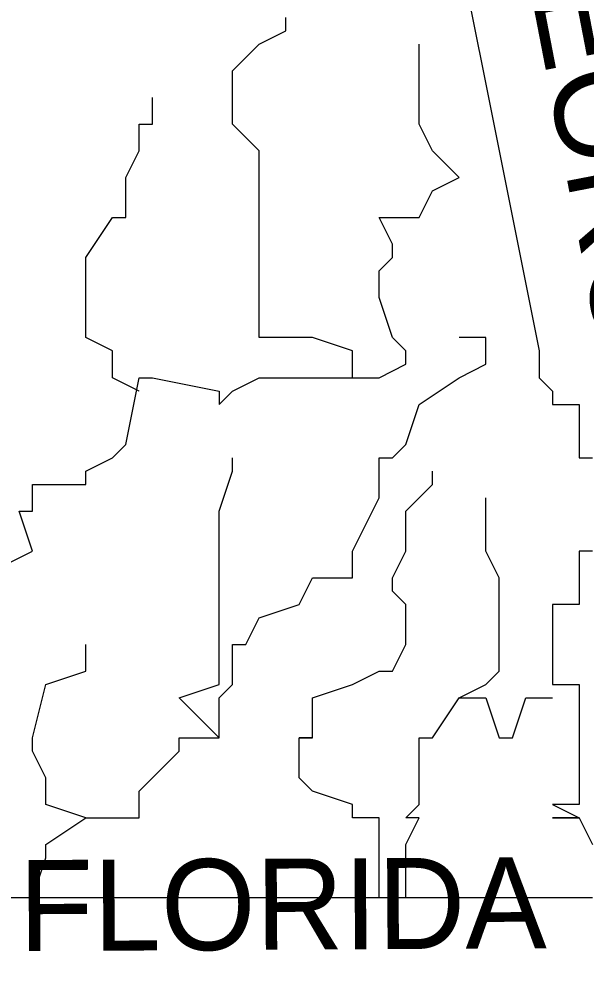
# Model space of a CAD drawing. Extents: x 1797478 to 1805176, y 246529 to 250952.
# Drawn here: x 1802981.062 to 1802983.296, y 250072.194 to 250075.933 of the extents above; entities that cross this region are included whole.
import ezdxf

# ---------------------------------------------------------------- set-up
doc = ezdxf.new("R2010")
doc.units = 0
doc.layers.add('great seal', color=7, linetype='Continuous')

msp = doc.modelspace()

# ---------------------------------------------------------------- linework, layer by layer
at = {"layer": 'great seal'}
msp.add_line((1802981.5349, 250074.4676), (1802981.5349, 250074.4676), dxfattribs=at)
msp.add_line((1802981.5349, 250074.4676), (1802981.5349, 250074.4676), dxfattribs=at)
msp.add_line((1802981.5349, 250074.4676), (1802981.5349, 250074.4676), dxfattribs=at)
msp.add_line((1802981.5349, 250074.4676), (1802981.5349, 250074.4676), dxfattribs=at)
msp.add_line((1802981.5349, 250074.4676), (1802981.5349, 250074.4676), dxfattribs=at)
msp.add_line((1802981.5349, 250074.4676), (1802981.5349, 250074.4676), dxfattribs=at)
for points in [[(1802979.7481, 250071.7875), (1802979.7481, 250073.6268), (1802980.2211, 250076.8851), (1802980.2211, 250076.9902), (1802980.2211, 250076.9902), (1802980.2211, 250076.9902), (1802980.0634, 250076.9902), (1802980.0634, 250077.0427), (1802980.2211, 250077.0427), (1802982.6385, 250076.9902), (1802983.1115, 250074.6253), (1802983.1115, 250074.5202), (1802983.164, 250074.4676), (1802983.164, 250074.4151), (1802983.164, 250074.4151), (1802983.2691, 250074.4151), (1802983.2691, 250074.2574), (1802983.2691, 250074.2049), (1802983.3217, 250074.2049)], [(1802979.7481, 250071.7875), (1802979.7481, 250073.6268), (1802980.2211, 250076.8851), (1802980.2211, 250076.9902), (1802980.2211, 250076.9902), (1802980.2211, 250076.9902), (1802980.0634, 250076.9902), (1802980.0634, 250077.0427), (1802980.2211, 250077.0427), (1802982.6385, 250076.9902), (1802983.1115, 250074.6253), (1802983.1115, 250074.5202), (1802983.164, 250074.4676), (1802983.164, 250074.4151), (1802983.164, 250074.4151), (1802983.2691, 250074.4151), (1802983.2691, 250074.2574), (1802983.2691, 250074.2049), (1802983.3217, 250074.2049)], [(1802979.7481, 250071.7875), (1802979.7481, 250073.6268), (1802980.2211, 250076.8851), (1802980.2211, 250076.9902), (1802980.2211, 250076.9902), (1802980.2211, 250076.9902), (1802980.0634, 250076.9902), (1802980.0634, 250077.0427), (1802980.2211, 250077.0427), (1802982.6385, 250076.9902), (1802983.1115, 250074.6253), (1802983.1115, 250074.5202), (1802983.164, 250074.4676), (1802983.164, 250074.4151), (1802983.164, 250074.4151), (1802983.2691, 250074.4151), (1802983.2691, 250074.2574), (1802983.2691, 250074.2049), (1802983.3217, 250074.2049)], [(1802982.3757, 250074.5202), (1802982.3757, 250074.6253), (1802982.2181, 250074.6779), (1802982.1655, 250074.6779), (1802982.0079, 250074.6779), (1802982.0079, 250074.9406), (1802982.0079, 250074.9406), (1802982.0079, 250074.9932), (1802982.0079, 250075.1508), (1802982.0079, 250075.2559), (1802982.0079, 250075.4136), (1802981.9028, 250075.5187), (1802981.9028, 250075.7289), (1802982.0079, 250075.834), (1802982.113, 250075.8866), (1802982.113, 250075.9391)], [(1802982.3757, 250074.5202), (1802982.3757, 250074.6253), (1802982.2181, 250074.6779), (1802982.1655, 250074.6779), (1802982.0079, 250074.6779), (1802982.0079, 250074.9406), (1802982.0079, 250074.9406), (1802982.0079, 250074.9932), (1802982.0079, 250075.1508), (1802982.0079, 250075.2559), (1802982.0079, 250075.4136), (1802981.9028, 250075.5187), (1802981.9028, 250075.7289), (1802982.0079, 250075.834), (1802982.113, 250075.8866), (1802982.113, 250075.9391)], [(1802982.3757, 250074.5202), (1802982.3757, 250074.6253), (1802982.2181, 250074.6779), (1802982.1655, 250074.6779), (1802982.0079, 250074.6779), (1802982.0079, 250074.9406), (1802982.0079, 250074.9406), (1802982.0079, 250074.9932), (1802982.0079, 250075.1508), (1802982.0079, 250075.2559), (1802982.0079, 250075.4136), (1802981.9028, 250075.5187), (1802981.9028, 250075.7289), (1802982.0079, 250075.834), (1802982.113, 250075.8866), (1802982.113, 250075.9391)], [(1802981.0094, 250073.7845), (1802981.1145, 250073.837), (1802981.0619, 250073.9947), (1802981.1145, 250073.9947), (1802981.1145, 250074.0998), (1802981.3247, 250074.0998), (1802981.3247, 250074.1523), (1802981.3247, 250074.1523), (1802981.4298, 250074.2049), (1802981.4823, 250074.2574), (1802981.5349, 250074.5202), (1802981.5874, 250074.5202), (1802981.8502, 250074.4676), (1802981.8502, 250074.4151), (1802981.9028, 250074.4676), (1802982.0079, 250074.5202), (1802982.1655, 250074.5202), (1802982.3757, 250074.5202), (1802982.4808, 250074.5202), (1802982.5859, 250074.5728), (1802982.5859, 250074.6253), (1802982.5334, 250074.6779), (1802982.5334, 250074.6779), (1802982.4808, 250074.8355), (1802982.4808, 250074.9406), (1802982.5334, 250074.9932), (1802982.5334, 250075.0457), (1802982.4808, 250075.1508), (1802982.6385, 250075.1508), (1802982.691, 250075.2559), (1802982.7962, 250075.3085), (1802982.691, 250075.4136), (1802982.691, 250075.4136), (1802982.6385, 250075.5187), (1802982.6385, 250075.6238), (1802982.6385, 250075.834)], [(1802981.0094, 250073.7845), (1802981.1145, 250073.837), (1802981.0619, 250073.9947), (1802981.1145, 250073.9947), (1802981.1145, 250074.0998), (1802981.3247, 250074.0998), (1802981.3247, 250074.1523), (1802981.3247, 250074.1523), (1802981.4298, 250074.2049), (1802981.4823, 250074.2574), (1802981.5349, 250074.5202), (1802981.5874, 250074.5202), (1802981.8502, 250074.4676), (1802981.8502, 250074.4151), (1802981.9028, 250074.4676), (1802982.0079, 250074.5202), (1802982.1655, 250074.5202), (1802982.3757, 250074.5202), (1802982.4808, 250074.5202), (1802982.5859, 250074.5728), (1802982.5859, 250074.6253), (1802982.5334, 250074.6779), (1802982.5334, 250074.6779), (1802982.4808, 250074.8355), (1802982.4808, 250074.9406), (1802982.5334, 250074.9932), (1802982.5334, 250075.0457), (1802982.4808, 250075.1508), (1802982.6385, 250075.1508), (1802982.691, 250075.2559), (1802982.7962, 250075.3085), (1802982.691, 250075.4136), (1802982.691, 250075.4136), (1802982.6385, 250075.5187), (1802982.6385, 250075.6238), (1802982.6385, 250075.834)], [(1802981.0094, 250073.7845), (1802981.1145, 250073.837), (1802981.0619, 250073.9947), (1802981.1145, 250073.9947), (1802981.1145, 250074.0998), (1802981.3247, 250074.0998), (1802981.3247, 250074.1523), (1802981.3247, 250074.1523), (1802981.4298, 250074.2049), (1802981.4823, 250074.2574), (1802981.5349, 250074.5202), (1802981.5874, 250074.5202), (1802981.8502, 250074.4676), (1802981.8502, 250074.4151), (1802981.9028, 250074.4676), (1802982.0079, 250074.5202), (1802982.1655, 250074.5202), (1802982.3757, 250074.5202), (1802982.4808, 250074.5202), (1802982.5859, 250074.5728), (1802982.5859, 250074.6253), (1802982.5334, 250074.6779), (1802982.5334, 250074.6779), (1802982.4808, 250074.8355), (1802982.4808, 250074.9406), (1802982.5334, 250074.9932), (1802982.5334, 250075.0457), (1802982.4808, 250075.1508), (1802982.6385, 250075.1508), (1802982.691, 250075.2559), (1802982.7962, 250075.3085), (1802982.691, 250075.4136), (1802982.691, 250075.4136), (1802982.6385, 250075.5187), (1802982.6385, 250075.6238), (1802982.6385, 250075.834)], [(1802981.5349, 250074.4676), (1802981.4298, 250074.5202), (1802981.4298, 250074.5728), (1802981.4298, 250074.6253), (1802981.3247, 250074.6779), (1802981.3247, 250074.8355), (1802981.3247, 250074.9406), (1802981.3247, 250074.9932), (1802981.3247, 250074.9932), (1802981.4298, 250075.1508), (1802981.4823, 250075.1508), (1802981.4823, 250075.3085), (1802981.5349, 250075.4136), (1802981.5349, 250075.4136), (1802981.5349, 250075.5187), (1802981.5874, 250075.5187), (1802981.5874, 250075.6238)], [(1802981.5349, 250074.4676), (1802981.4298, 250074.5202), (1802981.4298, 250074.5728), (1802981.4298, 250074.6253), (1802981.3247, 250074.6779), (1802981.3247, 250074.8355), (1802981.3247, 250074.9406), (1802981.3247, 250074.9932), (1802981.3247, 250074.9932), (1802981.4298, 250075.1508), (1802981.4823, 250075.1508), (1802981.4823, 250075.3085), (1802981.5349, 250075.4136), (1802981.5349, 250075.4136), (1802981.5349, 250075.5187), (1802981.5874, 250075.5187), (1802981.5874, 250075.6238)], [(1802981.5349, 250074.4676), (1802981.4298, 250074.5202), (1802981.4298, 250074.5728), (1802981.4298, 250074.6253), (1802981.3247, 250074.6779), (1802981.3247, 250074.8355), (1802981.3247, 250074.9406), (1802981.3247, 250074.9932), (1802981.3247, 250074.9932), (1802981.4298, 250075.1508), (1802981.4823, 250075.1508), (1802981.4823, 250075.3085), (1802981.5349, 250075.4136), (1802981.5349, 250075.4136), (1802981.5349, 250075.5187), (1802981.5874, 250075.5187), (1802981.5874, 250075.6238)], [(1802981.8502, 250073.1013), (1802981.8502, 250073.1013), (1802981.8502, 250073.2589), (1802981.9028, 250073.3115), (1802981.9028, 250073.364), (1802981.9028, 250073.4691), (1802981.9553, 250073.4691), (1802982.0079, 250073.5743), (1802982.1655, 250073.6268), (1802982.2181, 250073.7319), (1802982.3757, 250073.7319), (1802982.3757, 250073.837), (1802982.4808, 250074.0472), (1802982.4808, 250074.1523), (1802982.4808, 250074.1523), (1802982.4808, 250074.2049), (1802982.5334, 250074.2049), (1802982.5859, 250074.2574), (1802982.6385, 250074.4151), (1802982.7962, 250074.5202), (1802982.9013, 250074.5728), (1802982.9013, 250074.6253), (1802982.9013, 250074.6779), (1802982.7962, 250074.6779)], [(1802981.8502, 250073.1013), (1802981.8502, 250073.1013), (1802981.8502, 250073.2589), (1802981.9028, 250073.3115), (1802981.9028, 250073.364), (1802981.9028, 250073.4691), (1802981.9553, 250073.4691), (1802982.0079, 250073.5743), (1802982.1655, 250073.6268), (1802982.2181, 250073.7319), (1802982.3757, 250073.7319), (1802982.3757, 250073.837), (1802982.4808, 250074.0472), (1802982.4808, 250074.1523), (1802982.4808, 250074.1523), (1802982.4808, 250074.2049), (1802982.5334, 250074.2049), (1802982.5859, 250074.2574), (1802982.6385, 250074.4151), (1802982.7962, 250074.5202), (1802982.9013, 250074.5728), (1802982.9013, 250074.6253), (1802982.9013, 250074.6779), (1802982.7962, 250074.6779)], [(1802981.8502, 250073.1013), (1802981.8502, 250073.1013), (1802981.8502, 250073.2589), (1802981.9028, 250073.3115), (1802981.9028, 250073.364), (1802981.9028, 250073.4691), (1802981.9553, 250073.4691), (1802982.0079, 250073.5743), (1802982.1655, 250073.6268), (1802982.2181, 250073.7319), (1802982.3757, 250073.7319), (1802982.3757, 250073.837), (1802982.4808, 250074.0472), (1802982.4808, 250074.1523), (1802982.4808, 250074.1523), (1802982.4808, 250074.2049), (1802982.5334, 250074.2049), (1802982.5859, 250074.2574), (1802982.6385, 250074.4151), (1802982.7962, 250074.5202), (1802982.9013, 250074.5728), (1802982.9013, 250074.6253), (1802982.9013, 250074.6779), (1802982.7962, 250074.6779)], [(1802981.3247, 250072.786), (1802981.3247, 250072.786), (1802981.4298, 250072.786), (1802981.4823, 250072.786), (1802981.5349, 250072.786), (1802981.5349, 250072.8385), (1802981.5349, 250072.8911), (1802981.5874, 250072.9436), (1802981.6925, 250073.0487), (1802981.6925, 250073.1013), (1802981.8502, 250073.1013), (1802981.8502, 250073.1013), (1802981.6925, 250073.2589), (1802981.8502, 250073.3115), (1802981.8502, 250073.364), (1802981.8502, 250073.4691), (1802981.8502, 250073.5743), (1802981.8502, 250073.6268), (1802981.8502, 250073.7319), (1802981.8502, 250073.7319), (1802981.8502, 250073.837), (1802981.8502, 250073.9947), (1802981.9028, 250074.1523), (1802981.9028, 250074.1523), (1802981.9028, 250074.2049)], [(1802981.3247, 250072.786), (1802981.3247, 250072.786), (1802981.4298, 250072.786), (1802981.4823, 250072.786), (1802981.5349, 250072.786), (1802981.5349, 250072.8385), (1802981.5349, 250072.8911), (1802981.5874, 250072.9436), (1802981.6925, 250073.0487), (1802981.6925, 250073.1013), (1802981.8502, 250073.1013), (1802981.8502, 250073.1013), (1802981.6925, 250073.2589), (1802981.8502, 250073.3115), (1802981.8502, 250073.364), (1802981.8502, 250073.4691), (1802981.8502, 250073.5743), (1802981.8502, 250073.6268), (1802981.8502, 250073.7319), (1802981.8502, 250073.7319), (1802981.8502, 250073.837), (1802981.8502, 250073.9947), (1802981.9028, 250074.1523), (1802981.9028, 250074.1523), (1802981.9028, 250074.2049)], [(1802981.3247, 250072.786), (1802981.3247, 250072.786), (1802981.4298, 250072.786), (1802981.4823, 250072.786), (1802981.5349, 250072.786), (1802981.5349, 250072.8385), (1802981.5349, 250072.8911), (1802981.5874, 250072.9436), (1802981.6925, 250073.0487), (1802981.6925, 250073.1013), (1802981.8502, 250073.1013), (1802981.8502, 250073.1013), (1802981.6925, 250073.2589), (1802981.8502, 250073.3115), (1802981.8502, 250073.364), (1802981.8502, 250073.4691), (1802981.8502, 250073.5743), (1802981.8502, 250073.6268), (1802981.8502, 250073.7319), (1802981.8502, 250073.7319), (1802981.8502, 250073.837), (1802981.8502, 250073.9947), (1802981.9028, 250074.1523), (1802981.9028, 250074.1523), (1802981.9028, 250074.2049)], [(1802982.4808, 250072.4706), (1802982.4808, 250072.6283), (1802982.4808, 250072.6809), (1802982.4808, 250072.786), (1802982.4808, 250072.786), (1802982.3757, 250072.786), (1802982.3757, 250072.8385), (1802982.2181, 250072.8911), (1802982.1655, 250072.9436), (1802982.1655, 250073.0487), (1802982.1655, 250073.1013), (1802982.2181, 250073.1013), (1802982.1655, 250073.1013), (1802982.2181, 250073.1013), (1802982.2181, 250073.2589), (1802982.3757, 250073.3115), (1802982.4808, 250073.364), (1802982.4808, 250073.364), (1802982.5334, 250073.364), (1802982.5859, 250073.4691), (1802982.5859, 250073.4691), (1802982.5859, 250073.5743), (1802982.5859, 250073.6268), (1802982.5859, 250073.6268), (1802982.5334, 250073.6794), (1802982.5334, 250073.7319), (1802982.5859, 250073.837), (1802982.5859, 250073.9947), (1802982.6385, 250074.0472), (1802982.691, 250074.0998), (1802982.691, 250074.1523)], [(1802982.4808, 250072.4706), (1802982.4808, 250072.6283), (1802982.4808, 250072.6809), (1802982.4808, 250072.786), (1802982.4808, 250072.786), (1802982.3757, 250072.786), (1802982.3757, 250072.8385), (1802982.2181, 250072.8911), (1802982.1655, 250072.9436), (1802982.1655, 250073.0487), (1802982.1655, 250073.1013), (1802982.2181, 250073.1013), (1802982.1655, 250073.1013), (1802982.2181, 250073.1013), (1802982.2181, 250073.2589), (1802982.3757, 250073.3115), (1802982.4808, 250073.364), (1802982.4808, 250073.364), (1802982.5334, 250073.364), (1802982.5859, 250073.4691), (1802982.5859, 250073.4691), (1802982.5859, 250073.5743), (1802982.5859, 250073.6268), (1802982.5859, 250073.6268), (1802982.5334, 250073.6794), (1802982.5334, 250073.7319), (1802982.5859, 250073.837), (1802982.5859, 250073.9947), (1802982.6385, 250074.0472), (1802982.691, 250074.0998), (1802982.691, 250074.1523)], [(1802982.4808, 250072.4706), (1802982.4808, 250072.6283), (1802982.4808, 250072.6809), (1802982.4808, 250072.786), (1802982.4808, 250072.786), (1802982.3757, 250072.786), (1802982.3757, 250072.8385), (1802982.2181, 250072.8911), (1802982.1655, 250072.9436), (1802982.1655, 250073.0487), (1802982.1655, 250073.1013), (1802982.2181, 250073.1013), (1802982.1655, 250073.1013), (1802982.2181, 250073.1013), (1802982.2181, 250073.2589), (1802982.3757, 250073.3115), (1802982.4808, 250073.364), (1802982.4808, 250073.364), (1802982.5334, 250073.364), (1802982.5859, 250073.4691), (1802982.5859, 250073.4691), (1802982.5859, 250073.5743), (1802982.5859, 250073.6268), (1802982.5859, 250073.6268), (1802982.5334, 250073.6794), (1802982.5334, 250073.7319), (1802982.5859, 250073.837), (1802982.5859, 250073.9947), (1802982.6385, 250074.0472), (1802982.691, 250074.0998), (1802982.691, 250074.1523)], [(1802982.7962, 250073.2589), (1802982.7962, 250073.2589), (1802982.9013, 250073.3115), (1802982.9538, 250073.364), (1802982.9538, 250073.364), (1802982.9538, 250073.4691), (1802982.9538, 250073.5743), (1802982.9538, 250073.6268), (1802982.9538, 250073.6794), (1802982.9538, 250073.7319), (1802982.9013, 250073.837), (1802982.9013, 250073.837), (1802982.9013, 250074.0472)], [(1802982.7962, 250073.2589), (1802982.7962, 250073.2589), (1802982.9013, 250073.3115), (1802982.9538, 250073.364), (1802982.9538, 250073.364), (1802982.9538, 250073.4691), (1802982.9538, 250073.5743), (1802982.9538, 250073.6268), (1802982.9538, 250073.6794), (1802982.9538, 250073.7319), (1802982.9013, 250073.837), (1802982.9013, 250073.837), (1802982.9013, 250074.0472)], [(1802982.7962, 250073.2589), (1802982.7962, 250073.2589), (1802982.9013, 250073.3115), (1802982.9538, 250073.364), (1802982.9538, 250073.364), (1802982.9538, 250073.4691), (1802982.9538, 250073.5743), (1802982.9538, 250073.6268), (1802982.9538, 250073.6794), (1802982.9538, 250073.7319), (1802982.9013, 250073.837), (1802982.9013, 250073.837), (1802982.9013, 250074.0472)], [(1802983.3217, 250073.837), (1802983.2691, 250073.837), (1802983.2691, 250073.837), (1802983.2691, 250073.837), (1802983.2691, 250073.7845), (1802983.2691, 250073.7319), (1802983.2691, 250073.7319), (1802983.2691, 250073.7319), (1802983.2691, 250073.7319), (1802983.2691, 250073.7319), (1802983.2691, 250073.6794), (1802983.2691, 250073.6794), (1802983.2691, 250073.6794), (1802983.2691, 250073.6268), (1802983.2691, 250073.6268), (1802983.164, 250073.6268), (1802983.164, 250073.6268), (1802983.164, 250073.6268), (1802983.164, 250073.5743), (1802983.164, 250073.5743), (1802983.164, 250073.4691), (1802983.164, 250073.4691), (1802983.164, 250073.4691), (1802983.164, 250073.4691), (1802983.164, 250073.4691), (1802983.164, 250073.4691), (1802983.164, 250073.4691), (1802983.164, 250073.364), (1802983.164, 250073.364), (1802983.164, 250073.364), (1802983.164, 250073.364), (1802983.164, 250073.364), (1802983.164, 250073.364), (1802983.164, 250073.3115), (1802983.2691, 250073.3115), (1802983.2691, 250073.2589), (1802983.2691, 250073.2589), (1802983.2691, 250073.2589), (1802983.2691, 250073.1013), (1802983.2691, 250073.1013), (1802983.2691, 250073.1013), (1802983.2691, 250073.1013), (1802983.2691, 250073.1013), (1802983.2691, 250073.1013), (1802983.2691, 250073.0487), (1802983.2691, 250072.9436), (1802983.2691, 250072.9436), (1802983.2691, 250072.9436), (1802983.2691, 250072.8911), (1802983.2691, 250072.8911), (1802983.2691, 250072.8385), (1802983.2691, 250072.8385), (1802983.164, 250072.8385), (1802983.164, 250072.8385), (1802983.164, 250072.8385), (1802983.164, 250072.8385), (1802983.2691, 250072.786), (1802983.2691, 250072.786), (1802983.164, 250072.786), (1802983.2691, 250072.786), (1802983.2691, 250072.786), (1802983.2691, 250072.786), (1802983.3217, 250072.6809)], [(1802983.3217, 250073.837), (1802983.2691, 250073.837), (1802983.2691, 250073.837), (1802983.2691, 250073.837), (1802983.2691, 250073.7845), (1802983.2691, 250073.7319), (1802983.2691, 250073.7319), (1802983.2691, 250073.7319), (1802983.2691, 250073.7319), (1802983.2691, 250073.7319), (1802983.2691, 250073.6794), (1802983.2691, 250073.6794), (1802983.2691, 250073.6794), (1802983.2691, 250073.6268), (1802983.2691, 250073.6268), (1802983.164, 250073.6268), (1802983.164, 250073.6268), (1802983.164, 250073.6268), (1802983.164, 250073.5743), (1802983.164, 250073.5743), (1802983.164, 250073.4691), (1802983.164, 250073.4691), (1802983.164, 250073.4691), (1802983.164, 250073.4691), (1802983.164, 250073.4691), (1802983.164, 250073.4691), (1802983.164, 250073.4691), (1802983.164, 250073.364), (1802983.164, 250073.364), (1802983.164, 250073.364), (1802983.164, 250073.364), (1802983.164, 250073.364), (1802983.164, 250073.364), (1802983.164, 250073.3115), (1802983.2691, 250073.3115), (1802983.2691, 250073.2589), (1802983.2691, 250073.2589), (1802983.2691, 250073.2589), (1802983.2691, 250073.1013), (1802983.2691, 250073.1013), (1802983.2691, 250073.1013), (1802983.2691, 250073.1013), (1802983.2691, 250073.1013), (1802983.2691, 250073.1013), (1802983.2691, 250073.0487), (1802983.2691, 250072.9436), (1802983.2691, 250072.9436), (1802983.2691, 250072.9436), (1802983.2691, 250072.8911), (1802983.2691, 250072.8911), (1802983.2691, 250072.8385), (1802983.2691, 250072.8385), (1802983.164, 250072.8385), (1802983.164, 250072.8385), (1802983.164, 250072.8385), (1802983.164, 250072.8385), (1802983.2691, 250072.786), (1802983.2691, 250072.786), (1802983.164, 250072.786), (1802983.2691, 250072.786), (1802983.2691, 250072.786), (1802983.2691, 250072.786), (1802983.3217, 250072.6809)], [(1802983.3217, 250073.837), (1802983.2691, 250073.837), (1802983.2691, 250073.837), (1802983.2691, 250073.837), (1802983.2691, 250073.7845), (1802983.2691, 250073.7319), (1802983.2691, 250073.7319), (1802983.2691, 250073.7319), (1802983.2691, 250073.7319), (1802983.2691, 250073.7319), (1802983.2691, 250073.6794), (1802983.2691, 250073.6794), (1802983.2691, 250073.6794), (1802983.2691, 250073.6268), (1802983.2691, 250073.6268), (1802983.164, 250073.6268), (1802983.164, 250073.6268), (1802983.164, 250073.6268), (1802983.164, 250073.5743), (1802983.164, 250073.5743), (1802983.164, 250073.4691), (1802983.164, 250073.4691), (1802983.164, 250073.4691), (1802983.164, 250073.4691), (1802983.164, 250073.4691), (1802983.164, 250073.4691), (1802983.164, 250073.4691), (1802983.164, 250073.364), (1802983.164, 250073.364), (1802983.164, 250073.364), (1802983.164, 250073.364), (1802983.164, 250073.364), (1802983.164, 250073.364), (1802983.164, 250073.3115), (1802983.2691, 250073.3115), (1802983.2691, 250073.2589), (1802983.2691, 250073.2589), (1802983.2691, 250073.2589), (1802983.2691, 250073.1013), (1802983.2691, 250073.1013), (1802983.2691, 250073.1013), (1802983.2691, 250073.1013), (1802983.2691, 250073.1013), (1802983.2691, 250073.1013), (1802983.2691, 250073.0487), (1802983.2691, 250072.9436), (1802983.2691, 250072.9436), (1802983.2691, 250072.9436), (1802983.2691, 250072.8911), (1802983.2691, 250072.8911), (1802983.2691, 250072.8385), (1802983.2691, 250072.8385), (1802983.164, 250072.8385), (1802983.164, 250072.8385), (1802983.164, 250072.8385), (1802983.164, 250072.8385), (1802983.2691, 250072.786), (1802983.2691, 250072.786), (1802983.164, 250072.786), (1802983.2691, 250072.786), (1802983.2691, 250072.786), (1802983.2691, 250072.786), (1802983.3217, 250072.6809)], [(1802981.1145, 250072.4706), (1802981.167, 250072.6283), (1802981.167, 250072.6809), (1802981.3247, 250072.786), (1802981.3247, 250072.786), (1802981.3247, 250072.786), (1802981.167, 250072.8385), (1802981.167, 250072.8911), (1802981.167, 250072.9436), (1802981.1145, 250073.0487), (1802981.1145, 250073.1013), (1802981.1145, 250073.1013), (1802981.167, 250073.3115), (1802981.3247, 250073.364), (1802981.3247, 250073.4691)], [(1802981.1145, 250072.4706), (1802981.167, 250072.6283), (1802981.167, 250072.6809), (1802981.3247, 250072.786), (1802981.3247, 250072.786), (1802981.3247, 250072.786), (1802981.167, 250072.8385), (1802981.167, 250072.8911), (1802981.167, 250072.9436), (1802981.1145, 250073.0487), (1802981.1145, 250073.1013), (1802981.1145, 250073.1013), (1802981.167, 250073.3115), (1802981.3247, 250073.364), (1802981.3247, 250073.4691)], [(1802981.1145, 250072.4706), (1802981.167, 250072.6283), (1802981.167, 250072.6809), (1802981.3247, 250072.786), (1802981.3247, 250072.786), (1802981.3247, 250072.786), (1802981.167, 250072.8385), (1802981.167, 250072.8911), (1802981.167, 250072.9436), (1802981.1145, 250073.0487), (1802981.1145, 250073.1013), (1802981.1145, 250073.1013), (1802981.167, 250073.3115), (1802981.3247, 250073.364), (1802981.3247, 250073.4691)], [(1802982.5859, 250072.4706), (1802982.5859, 250072.6283), (1802982.5859, 250072.6283), (1802982.5859, 250072.6809), (1802982.6385, 250072.786), (1802982.5859, 250072.786), (1802982.6385, 250072.8385), (1802982.6385, 250072.8911), (1802982.6385, 250072.9436), (1802982.6385, 250072.9436), (1802982.6385, 250073.0487), (1802982.6385, 250073.1013), (1802982.691, 250073.1013), (1802982.7962, 250073.2589), (1802982.9013, 250073.2589), (1802982.9538, 250073.1013), (1802983.0064, 250073.1013), (1802983.0589, 250073.2589), (1802983.1115, 250073.2589), (1802983.164, 250073.2589)], [(1802982.5859, 250072.4706), (1802982.5859, 250072.6283), (1802982.5859, 250072.6283), (1802982.5859, 250072.6809), (1802982.6385, 250072.786), (1802982.5859, 250072.786), (1802982.6385, 250072.8385), (1802982.6385, 250072.8911), (1802982.6385, 250072.9436), (1802982.6385, 250072.9436), (1802982.6385, 250073.0487), (1802982.6385, 250073.1013), (1802982.691, 250073.1013), (1802982.7962, 250073.2589), (1802982.9013, 250073.2589), (1802982.9538, 250073.1013), (1802983.0064, 250073.1013), (1802983.0589, 250073.2589), (1802983.1115, 250073.2589), (1802983.164, 250073.2589)], [(1802982.5859, 250072.4706), (1802982.5859, 250072.6283), (1802982.5859, 250072.6283), (1802982.5859, 250072.6809), (1802982.6385, 250072.786), (1802982.5859, 250072.786), (1802982.6385, 250072.8385), (1802982.6385, 250072.8911), (1802982.6385, 250072.9436), (1802982.6385, 250072.9436), (1802982.6385, 250073.0487), (1802982.6385, 250073.1013), (1802982.691, 250073.1013), (1802982.7962, 250073.2589), (1802982.9013, 250073.2589), (1802982.9538, 250073.1013), (1802983.0064, 250073.1013), (1802983.0589, 250073.2589), (1802983.1115, 250073.2589), (1802983.164, 250073.2589)], [(1802983.3217, 250072.4706), (1802980.6415, 250072.4706), (1802980.6415, 250072.4181), (1802980.6415, 250072.4181)], [(1802983.3217, 250072.4706), (1802980.6415, 250072.4706), (1802980.6415, 250072.4181), (1802980.6415, 250072.4181)], [(1802983.3217, 250072.4706), (1802980.6415, 250072.4706), (1802980.6415, 250072.4181), (1802980.6415, 250072.4181)]]:
    msp.add_lwpolyline(points, dxfattribs=at)
for radius in [4.5988, 4.5988, 4.5988, 4.4778, 4.4778, 4.4778, 3.5557, 3.5557, 3.5557, 3.4444, 3.4444, 3.4444]:
    msp.add_circle((1802981.5384, 250074.4308), radius, dxfattribs=at)

# ---------------------------------------------------------------- texts
for s, height, rotation, p in [('GEORGIA', 0.36892, 280.9296, (1802983.0064, 250076.4121)), ('GEORGIA', 0.36892, 280.9296, (1802983.0064, 250076.4121)), ('GEORGIA', 0.36892, 280.9296, (1802983.0064, 250076.4121)), ('FLORIDA', 0.35883, 0.3238, (1802981.0619, 250072.2604)), ('FLORIDA', 0.35883, 0.3238, (1802981.0619, 250072.2604)), ('FLORIDA', 0.35883, 0.3238, (1802981.0619, 250072.2604))]:
    msp.add_text(s, height=height, rotation=rotation, dxfattribs=at).set_placement(p)

doc.saveas('drawing.dxf')
